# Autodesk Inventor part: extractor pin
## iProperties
Created: 2006-04
Part Number: extractor pin
Document SubType Name: Modeling
Designer: Калинин
Author: Калинин
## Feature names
1. Вращение1 [Revolution]
